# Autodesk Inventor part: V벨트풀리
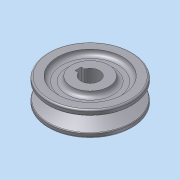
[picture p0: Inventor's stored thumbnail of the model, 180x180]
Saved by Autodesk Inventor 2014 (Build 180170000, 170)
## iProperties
Created: 2015-03
Part Number: V벨트풀리
Material: 강
Document SubType Name: Modeling
Designer: KYOUNG IL JANG
Density: 1 g/cm^3
Appearance: 강철
CustomPartVersion: 1
Author: KYOUNG IL JANG
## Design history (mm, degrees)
sketch "주 스케치"
  geometry: L1 (0, 16)-(27, 16); L2 (27, 16)-(27, 12.861); L3 (27, 12.861)-(16, 9.498); L4 (16, 9.498)-(16, 6.502); L5 (16, 6.502)-(27, 3.139); L6 (27, 3.139)-(27, 0); L7 (27, 0)-(0, 0); L8 (25, 12.25)-(25, 3.75); L9 (16, 8)-(25, 8); L10 (27, 12.861)-(27, 3.139); L11 (0, -3)-(0, 18) reference; L12 (0, 0)-(0, 16)
  constraints: 22 end point, 5 perpendicular, 2 collinear, 2 midpoint, 2 point on line, 1 parallel
  dimensions: "d0" = 8.5 distance of L8.start L8.end (= da_Bw); "d1" = 34 deg angle of L3 L5 (= da_Alfa); "d2" = 2 distance between parallel lines of L2 L8 (= da_c); "d6" = 16 distance between parallel lines of L7 L1 (computed from d5, da_ng, da_Sg); "d21" = 50 diameter of L8 L11 (= da_Dw); "d25" = 11 distance between parallel lines of L4 L10 (= da_Hd); "d27" = 8 distance between parallel lines of L7 L9 (= da_Se)
node "벨트 평면"
revolve "본체" stored, may be unused: angle "d7" = 90 deg
revolve "그루브" stored, may be unused: angle "d15" = 90 deg
feature "허브 키홈"
fillet "모깎기3" dims "d28" = 0.5, "d29" = 1, "d30" = 1
sketch "스케치2"
  geometry: C1 r 12 at (0, 0); C2 r 21 at (0, 0); 1 further point
  constraints: 2 centre point, 2 coincident
  dimensions: "d31" = 24 diameter of C1; "d32" = 42 diameter of C2
extrude "돌출1" cut sketch "스케치2" distance "d33" = 3; taper "d34" = 0 deg
fillet "모깎기4" dims "d35" = 3
node "작업 평면2"
body "Solid1"
pattern_linear "그루브 패턴" dims "d18" = 12 (= da_Sg)
mirror "대칭1"
other parameters: "d5" = 8 (= da_Se), "da_Bw" = 8.5 [user parameter; used in 1 equation term], "da_Alfa" = 34 deg [user parameter; used in 1 equation term], "da_c" = 2 [user parameter; used in 1 equation term], "da_Dw" = 50 [user parameter; used in 1 equation term], "da_Hd" = 11 [user parameter; used in 1 equation term], "da_Se" = 8 [user parameter; used in 2 equation terms], "da_Sg" = 12 [user parameter; used in 2 equation terms], "da_r1" = 0 [user parameter], "da_r2" = 0 [user parameter], "d24" = 0, "d26" = 0
